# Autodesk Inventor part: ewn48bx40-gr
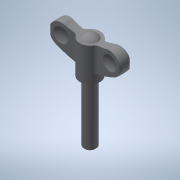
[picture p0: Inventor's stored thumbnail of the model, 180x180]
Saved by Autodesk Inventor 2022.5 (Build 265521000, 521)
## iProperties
Created: 2017-05
Part Number: ewn48bx40-gr
Material: 一般
Document SubType Name: Modeling
Designer: imaocorp
Density: 1 g/cm^3
Appearance: 既定
Author: imaocorp
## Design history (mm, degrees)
node "ewn48bx40-gr.x_t1"
node "ewn48bx40-gr"
node "Base1"
